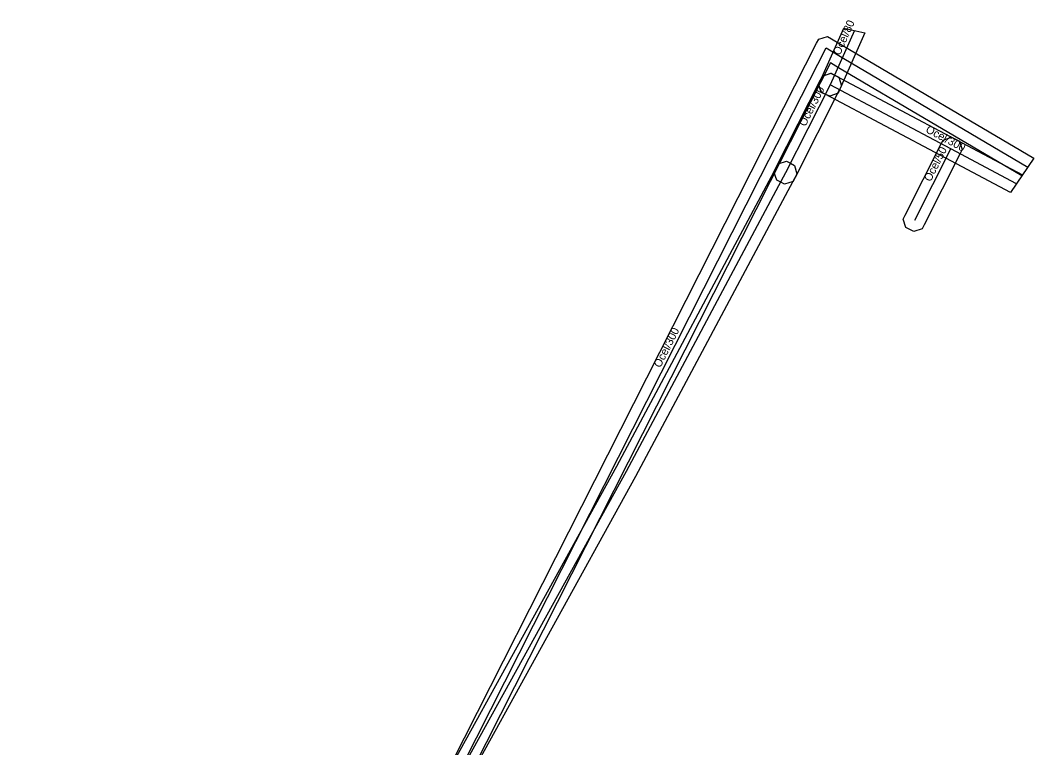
# Model space of a CAD drawing. Extents: x -702844 to -702342, y -1011731 to -1011542.
# Drawn here: x -702537.2 to -702442.3, y -1011610.2 to -1011542 of the extents above; entities that cross this region are included whole.
import ezdxf

# ---------------------------------------------------------------- set-up
doc = ezdxf.new("R2010")
doc.units = 0
for name, color, linetype in [('1', 7, 'Continuous'), ('14', 7, 'Continuous'), ('20', 7, 'Continuous'), ('24', 7, 'Continuous'), ('30', 7, 'Continuous')]:
    doc.layers.add(name, color=color, linetype=linetype)

msp = doc.modelspace()

# ---------------------------------------------------------------- linework, layer by layer
at = {"layer": '1'}
for points in [[(-702462.266, -1011547.683), (-702460.078, -1011542.787), (-702458.084, -1011543.226), (-702460.44, -1011548.499), (-702460.609, -1011548.877), (-702461.383, -1011549.173), (-702461.761, -1011549.004), (-702462.139, -1011548.835), (-702462.435, -1011548.061)], [(-702460.274, -1011548.174), (-702460.461, -1011548.543), (-702464.639, -1011556.782), (-702464.826, -1011557.151), (-702465.614, -1011557.409), (-702465.983, -1011557.222), (-702466.352, -1011557.035), (-702466.61, -1011556.247), (-702466.423, -1011555.878), (-702462.245, -1011547.639), (-702462.058, -1011547.27), (-702461.27, -1011547.012), (-702460.901, -1011547.199), (-702460.532, -1011547.386)], [(-702449.581, -1011553.206), (-702443.324, -1011556.529), (-702444.451, -1011558.195), (-702450.519, -1011554.972), (-702461.822, -1011548.974), (-702462.188, -1011548.78), (-702462.43, -1011547.988), (-702462.236, -1011547.622), (-702462.042, -1011547.256), (-702461.25, -1011547.014), (-702460.884, -1011547.208)], [(-702454.503, -1011560.682), (-702454.316, -1011560.313), (-702450.942, -1011553.638), (-702450.755, -1011553.268), (-702449.968, -1011553.01), (-702449.599, -1011553.197), (-702449.229, -1011553.384), (-702448.971, -1011554.171), (-702449.158, -1011554.54), (-702452.532, -1011561.215), (-702452.719, -1011561.585), (-702453.506, -1011561.843), (-702453.875, -1011561.656), (-702454.245, -1011561.469)]]:
    msp.add_lwpolyline(points, close=True, dxfattribs=at)
for points in [[(-702498.028, -1011614.104), (-702468.757, -1011556.234), (-702462.617, -1011544.187), (-702462.421, -1011543.801), (-702462.005, -1011543.681), (-702461.59, -1011543.56), (-702461.217, -1011543.78), (-702459.544, -1011544.769), (-702442.275, -1011554.978), (-702443.397, -1011556.638), (-702460.562, -1011546.491), (-702461.318, -1011546.044), (-702466.973, -1011557.14), (-702496.244, -1011615.006)], [(-702498.011, -1011614.071), (-702481.347, -1011583.848), (-702467.072, -1011557.095), (-702466.413, -1011555.86), (-702466.218, -1011555.494), (-702465.426, -1011555.253), (-702465.061, -1011555.448), (-702464.695, -1011555.643), (-702464.454, -1011556.435), (-702464.649, -1011556.8), (-702465.308, -1011558.037), (-702479.589, -1011584.802), (-702496.259, -1011615.037)]]:
    msp.add_lwpolyline(points, dxfattribs=at)
at = {"layer": '14'}
for points in [[(-702459.081, -1011543.007), (-702461.353, -1011548.091)], [(-702461.353, -1011548.091), (-702465.531, -1011556.33)], [(-702443.887, -1011557.362), (-702450.05, -1011554.089), (-702461.353, -1011548.091)], [(-702453.424, -1011560.764), (-702450.05, -1011554.089)], [(-702465.531, -1011556.33), (-702466.19, -1011557.566), (-702480.468, -1011584.325), (-702497.135, -1011614.554), (-702498.412, -1011616.873), (-702506.45, -1011631.454), (-702516.935, -1011650.464), (-702525.786, -1011663.419), (-702537.224, -1011673.368)]]:
    msp.add_lwpolyline(points, dxfattribs=at)
at = {"layer": '24'}
msp.add_lwpolyline([(-702506.196, -1011612.938), (-702505.877, -1011613.099), (-702503.549, -1011614.277), (-702498.331, -1011616.917), (-702497.136, -1011614.555), (-702467.865, -1011556.687), (-702461.726, -1011544.641), (-702460.053, -1011545.63), (-702442.836, -1011555.808)], dxfattribs=at)

# ---------------------------------------------------------------- texts
at = {"layer": '20'}
for s, rotation, p in [('Ocel/80', 65.92503, (-702460.438, -1011545.394)), ('Ocel/300', 63.11042, (-702463.665, -1011552.055)), ('Ocel/300', 332.04709, (-702452.464, -1011552.502)), ('Ocel/50', 63.18486, (-702451.937, -1011557.227))]:
    msp.add_text(s, height=0.75, rotation=rotation, dxfattribs=at).set_placement(p)
at = {"layer": '30'}
msp.add_text('Ocel/300', height=0.75, rotation=63.16864, dxfattribs=at).set_placement((-702477.261, -1011574.667))

doc.saveas('drawing.dxf')
